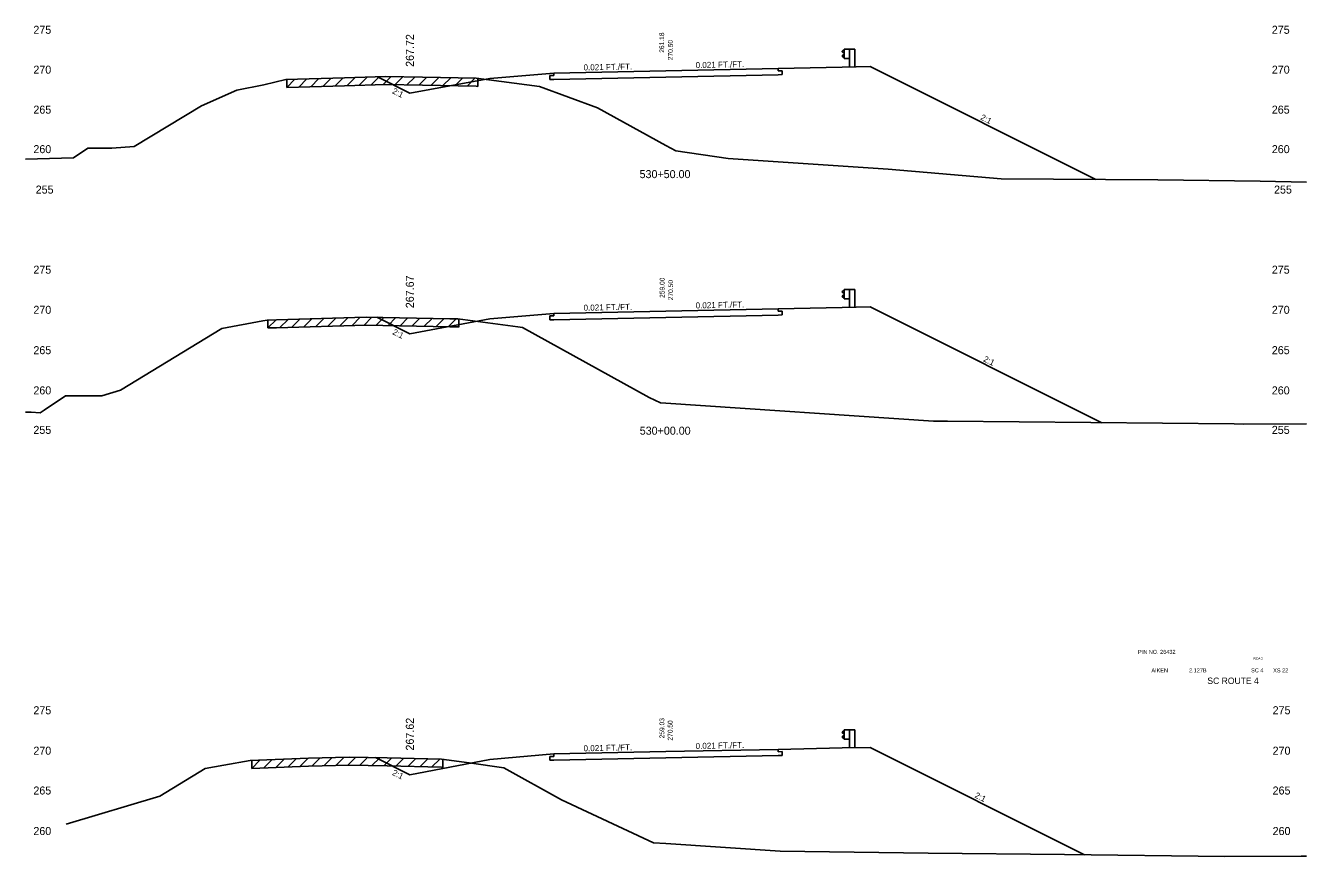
# Model space of a CAD drawing. Extents: x 883 to 1160, y 1002 to 4323.
# Drawn here: x 1000 to 1160, y 3492.4 to 3596.1 of the extents above; entities that cross this region are included whole.
import ezdxf

# ---------------------------------------------------------------- set-up
doc = ezdxf.new("R2010")
doc.units = 0
for name, color, linetype in [('Level 1', 7, 'Continuous'), ('Level 10', 7, 'Continuous'), ('Level 11', 7, 'Continuous'), ('Level 12', 7, 'Continuous'), ('Level 24', 7, 'Continuous'), ('Level 3', 7, 'Continuous'), ('Level 32', 7, 'Continuous'), ('Level 33', 7, 'Continuous'), ('Level 59', 7, 'Continuous'), ('Level 6', 7, 'Continuous'), ('Level 60', 7, 'Continuous'), ('Level 61', 7, 'Continuous'), ('Level 7', 7, 'Continuous')]:
    doc.layers.add(name, color=color, linetype=linetype)

msp = doc.modelspace()

# ---------------------------------------------------------------- linework, layer by layer
at = {"layer": 'Level 11'}
for p, q in [((1094, 3590.49), (1094, 3590.79)), ((1094.5, 3590.5), (1094, 3590.49)), ((1094.5, 3590.02), (1094.5, 3590.5)), ((1066, 3589.91), (1065.5, 3589.9)), ((1065.5, 3589.9), (1065.5, 3589.42)), ((1065.5, 3589.42), (1066, 3589.43)), ((1066, 3590.21), (1066, 3589.91)), ((1094, 3590.01), (1094.5, 3590.02)), ((1066, 3560.21), (1066, 3559.91)), ((1094, 3560.49), (1094, 3560.79)), ((1094.5, 3560.5), (1094, 3560.49)), ((1094, 3560.01), (1094.5, 3560.02)), ((1094.5, 3560.02), (1094.5, 3560.5)), ((1066, 3559.91), (1065.5, 3559.9)), ((1065.5, 3559.9), (1065.5, 3559.42)), ((1065.5, 3559.42), (1066, 3559.43)), ((1094, 3505.49), (1094, 3505.79)), ((1066, 3504.91), (1065.5, 3504.9)), ((1065.5, 3504.9), (1065.5, 3504.42)), ((1065.5, 3504.42), (1066, 3504.43)), ((1066, 3505.21), (1066, 3504.91)), ((1094.5, 3505.5), (1094, 3505.49)), ((1094, 3505.01), (1094.5, 3505.02)), ((1094.5, 3505.02), (1094.5, 3505.5))]:
    msp.add_line(p, q, dxfattribs=at)
at = {"layer": 'Level 12'}
for p, q in [((1080, 3589.72), (1066, 3589.43)), ((1094, 3590.01), (1080, 3589.72)), ((1094, 3560.01), (1080, 3559.72)), ((1080, 3559.72), (1066, 3559.43)), ((1080, 3504.72), (1066, 3504.43)), ((1094, 3505.01), (1080, 3504.72))]:
    msp.add_line(p, q, dxfattribs=at)
at = {"layer": 'Level 24'}
for p, q in [((1102.27, 3593.13), (1102, 3592.93)), ((1102, 3592.93), (1102, 3592.88)), ((1102, 3592.88), (1102.27, 3592.68)), ((1102, 3592.36), (1102.27, 3592.56)), ((1102, 3592.31), (1102, 3592.36)), ((1102.27, 3592.11), (1102, 3592.31)), ((1102.27, 3592.04), (1102.27, 3593.21)), ((1102.27, 3593.21), (1102.94, 3593.21)), ((1102.27, 3592.04), (1102.94, 3592.04)), ((1102.94, 3593.21), (1102.94, 3590.98)), ((1102.94, 3593.21), (1103.6, 3593.21)), ((1103.6, 3593.21), (1103.6, 3590.99)), ((1102.27, 3562.04), (1102.27, 3563.21)), ((1102.27, 3563.21), (1102.94, 3563.21)), ((1102.94, 3563.21), (1102.94, 3560.98)), ((1102.94, 3563.21), (1103.6, 3563.21)), ((1103.6, 3563.21), (1103.6, 3560.99)), ((1102.27, 3563.13), (1102, 3562.93)), ((1102, 3562.93), (1102, 3562.88)), ((1102, 3562.88), (1102.27, 3562.68)), ((1102, 3562.36), (1102.27, 3562.56)), ((1102, 3562.31), (1102, 3562.36)), ((1102.27, 3562.11), (1102, 3562.31)), ((1102.27, 3562.04), (1102.94, 3562.04)), ((1102.27, 3508.13), (1102, 3507.93)), ((1102, 3507.93), (1102, 3507.88)), ((1102, 3507.88), (1102.27, 3507.68)), ((1102, 3507.36), (1102.27, 3507.56)), ((1102, 3507.31), (1102, 3507.36)), ((1102.27, 3507.11), (1102, 3507.31)), ((1102.27, 3507.04), (1102.27, 3508.21)), ((1102.27, 3508.21), (1102.94, 3508.21)), ((1102.94, 3508.21), (1102.94, 3505.98)), ((1102.94, 3508.21), (1103.6, 3508.21)), ((1103.6, 3508.21), (1103.6, 3505.99)), ((1102.27, 3507.04), (1102.94, 3507.04))]:
    msp.add_line(p, q, dxfattribs=at)
at = {"layer": 'Level 59'}
for p, q in [((1066, 3590.21), (1080, 3590.5)), ((1080, 3590.5), (1094, 3590.79)), ((1066, 3560.21), (1080, 3560.5)), ((1080, 3560.5), (1094, 3560.79)), ((1080, 3505.5), (1094, 3505.79)), ((1066, 3505.21), (1080, 3505.5))]:
    msp.add_line(p, q, dxfattribs=at)
at = {"layer": 'Level 6'}
for p, q in [((1094, 3590.79), (1102, 3590.96)), ((1102, 3590.96), (1105.5, 3591.03)), ((1058, 3589.54), (1066, 3590.21)), ((1058, 3559.54), (1066, 3560.21)), ((1094, 3560.79), (1102, 3560.96)), ((1102, 3560.96), (1105.5, 3561.03)), ((1094, 3505.79), (1102, 3505.96)), ((1102, 3505.96), (1105.5, 3506.03)), ((1058, 3504.54), (1066, 3505.21))]:
    msp.add_line(p, q, dxfattribs=at)
at = {"layer": 'Level 60'}
for p, q in [((1029.78, 3588.74), (1032.49, 3589.4)), ((1032.49, 3589.4), (1039.84, 3589.62)), ((1039.84, 3589.62), (1044.97, 3589.77)), ((1044.97, 3589.77), (1049.56, 3589.7)), ((1049.56, 3589.7), (1056.28, 3589.56)), ((1056.28, 3589.56), (1059.45, 3589.15)), ((1059.45, 3589.15), (1064.2, 3588.53)), ((1021.96, 3586.13), (1026.38, 3588.1)), ((1026.38, 3588.1), (1029.78, 3588.74)), ((1064.2, 3588.53), (1071.46, 3585.88)), ((1013.58, 3581.05), (1021.96, 3586.13)), ((1071.46, 3585.88), (1080, 3581.18)), ((1005.98, 3579.65), (1007.78, 3580.84)), ((1007.78, 3580.84), (1010.77, 3580.84)), ((1010.77, 3580.84), (1013.58, 3581.05)), ((1080, 3581.18), (1081.21, 3580.51)), ((1000, 3579.48), (1005.98, 3579.65)), ((1081.21, 3580.51), (1087.78, 3579.53)), ((1087.78, 3579.53), (1107.77, 3578.22)), ((1107.77, 3578.22), (1121.85, 3577.01)), ((1121.85, 3577.01), (1141.44, 3576.87)), ((1141.44, 3576.87), (1154.24, 3576.73)), ((1154.24, 3576.73), (1160, 3576.59)), ((1024.5, 3558.32), (1029.63, 3559.29)), ((1029.63, 3559.29), (1030.16, 3559.38)), ((1030.16, 3559.38), (1031.34, 3559.43)), ((1031.34, 3559.43), (1042.55, 3559.76)), ((1042.55, 3559.76), (1053, 3559.54)), ((1053, 3559.54), (1053.98, 3559.52)), ((1053.98, 3559.52), (1061.49, 3558.52)), ((1061.49, 3558.52), (1062.08, 3558.44)), ((1062.08, 3558.44), (1077.9, 3549.7)), ((1011.84, 3550.64), (1024.5, 3558.32)), ((1009.51, 3549.94), (1011.84, 3550.64)), ((1002.3, 3548.14), (1005, 3549.94)), ((1005, 3549.94), (1009.51, 3549.94)), ((1077.9, 3549.7), (1079.32, 3549.04)), ((1079.32, 3549.04), (1080, 3549)), ((1080, 3549), (1113.42, 3546.77)), ((1000, 3547.87), (1000.7, 3547.88)), ((1000.7, 3547.88), (1001.8, 3547.78)), ((1001.8, 3547.78), (1002.3, 3548.14)), ((1113.42, 3546.77), (1115.15, 3546.74)), ((1115.15, 3546.74), (1150.98, 3546.41)), ((1150.98, 3546.41), (1152.2, 3546.4)), ((1152.2, 3546.4), (1160, 3546.43)), ((1024.76, 3503.83), (1028.05, 3504.4)), ((1028.05, 3504.4), (1035.36, 3504.68)), ((1035.36, 3504.68), (1040.44, 3504.83)), ((1040.44, 3504.83), (1045.17, 3504.73)), ((1045.17, 3504.73), (1051.97, 3504.56)), ((1051.97, 3504.56), (1055.39, 3504.1)), ((1055.39, 3504.1), (1059.73, 3503.48)), ((1016.77, 3499.94), (1022.45, 3503.4)), ((1022.45, 3503.4), (1024.76, 3503.83)), ((1059.73, 3503.48), (1066.96, 3499.48)), ((1005.07, 3496.43), (1016.77, 3499.94)), ((1066.96, 3499.48), (1078.44, 3494.13)), ((1078.44, 3494.13), (1080, 3494.03)), ((1080, 3494.03), (1094.26, 3493.08)), ((1094.26, 3493.08), (1112.77, 3492.83)), ((1112.77, 3492.83), (1129.77, 3492.67)), ((1129.77, 3492.67), (1149.8, 3492.43)), ((1149.8, 3492.43), (1159.33, 3492.47)), ((1159.33, 3492.47), (1160, 3492.47))]:
    msp.add_line(p, q, dxfattribs=at)
at = {"layer": 'Level 61'}
for p, q in [((1033.65, 3589.44), (1032.62, 3588.41)), ((1032.62, 3589.41), (1032.62, 3588.41)), ((1035.15, 3589.48), (1034.12, 3588.45)), ((1036.65, 3589.53), (1035.62, 3588.5)), ((1038.16, 3589.57), (1037.12, 3588.54)), ((1039.66, 3589.62), (1038.63, 3588.59)), ((1041.16, 3589.66), (1040.13, 3588.63)), ((1042.66, 3589.7), (1041.63, 3588.68)), ((1044.16, 3589.75), (1043.13, 3588.72)), ((1045.63, 3589.76), (1044.63, 3588.76)), ((1047.12, 3589.74), (1046.13, 3588.75)), ((1048.62, 3589.72), (1047.64, 3588.73)), ((1050.12, 3589.69), (1049.14, 3588.71)), ((1051.62, 3589.66), (1050.64, 3588.68)), ((1053.12, 3589.63), (1052.14, 3588.65)), ((1054.63, 3589.6), (1053.64, 3588.62)), ((1056.13, 3589.57), (1055.15, 3588.59)), ((1056.5, 3588.54), (1056.5, 3589.54)), ((1032.62, 3588.41), (1039.84, 3588.62)), ((1039.84, 3588.62), (1044.97, 3588.77)), ((1044.97, 3588.77), (1049.56, 3588.7)), ((1049.56, 3588.7), (1056.28, 3588.56)), ((1056.28, 3588.56), (1056.5, 3588.54)), ((1031.31, 3559.43), (1030.27, 3558.39)), ((1030.27, 3559.39), (1030.27, 3558.39)), ((1030.27, 3558.39), (1031.34, 3558.43)), ((1031.34, 3558.43), (1042.55, 3558.76)), ((1032.8, 3559.47), (1031.77, 3558.44)), ((1034.3, 3559.52), (1033.27, 3558.49)), ((1035.8, 3559.56), (1034.77, 3558.53)), ((1037.3, 3559.61), (1036.27, 3558.57)), ((1038.81, 3559.65), (1037.77, 3558.62)), ((1040.31, 3559.7), (1039.27, 3558.66)), ((1041.81, 3559.74), (1040.78, 3558.71)), ((1043.27, 3559.75), (1042.28, 3558.75)), ((1042.55, 3558.76), (1053, 3558.54)), ((1044.76, 3559.72), (1043.78, 3558.74)), ((1046.26, 3559.68), (1045.28, 3558.7)), ((1047.76, 3559.65), (1046.78, 3558.67)), ((1049.26, 3559.62), (1048.28, 3558.64)), ((1050.77, 3559.59), (1049.79, 3558.61)), ((1052.27, 3559.56), (1051.29, 3558.58)), ((1053.77, 3559.52), (1052.79, 3558.55)), ((1053, 3558.54), (1053.98, 3558.52)), ((1053.98, 3558.52), (1054.14, 3558.5)), ((1054.14, 3558.5), (1054.14, 3559.5)), ((1029.28, 3504.45), (1028.24, 3503.41)), ((1028.24, 3504.41), (1028.24, 3503.41)), ((1030.78, 3504.51), (1029.74, 3503.47)), ((1032.28, 3504.56), (1031.24, 3503.52)), ((1033.78, 3504.62), (1032.74, 3503.58)), ((1035.28, 3504.67), (1034.25, 3503.63)), ((1036.78, 3504.72), (1035.75, 3503.69)), ((1038.28, 3504.76), (1037.25, 3503.73)), ((1039.78, 3504.81), (1038.75, 3503.78)), ((1041.24, 3504.81), (1040.25, 3503.82)), ((1042.73, 3504.78), (1041.75, 3503.8)), ((1044.23, 3504.75), (1043.25, 3503.77)), ((1045.73, 3504.71), (1044.75, 3503.74)), ((1047.23, 3504.68), (1046.25, 3503.7)), ((1048.73, 3504.64), (1047.75, 3503.66)), ((1050.23, 3504.6), (1049.26, 3503.62)), ((1051.73, 3504.56), (1050.76, 3503.59)), ((1052.11, 3503.54), (1052.11, 3504.54)), ((1028.24, 3503.41), (1035.36, 3503.68)), ((1035.36, 3503.68), (1040.44, 3503.83)), ((1040.44, 3503.83), (1045.17, 3503.73)), ((1045.17, 3503.73), (1051.97, 3503.56)), ((1051.97, 3503.56), (1052.11, 3503.54))]:
    msp.add_line(p, q, dxfattribs=at)
at = {"layer": 'Level 7'}
for p, q in [((1105.5, 3591.03), (1133.71, 3576.92)), ((1043.95, 3589.74), (1048, 3587.72)), ((1048, 3587.72), (1058, 3589.54)), ((1105.5, 3561.03), (1134.43, 3546.56)), ((1043.86, 3559.73), (1048, 3557.67)), ((1048, 3557.67), (1058, 3559.54)), ((1105.5, 3506.03), (1132.28, 3492.64)), ((1043.72, 3504.76), (1048, 3502.62)), ((1048, 3502.62), (1058, 3504.54))]:
    msp.add_line(p, q, dxfattribs=at)

# ---------------------------------------------------------------- texts
at = {"layer": 'Level 1'}
for s, height, p in [('530+50.00', 1, (1076.7, 3577.1)), ('530+00.00', 1, (1076.72, 3545.07)), ('PIN NO. 26432', 0.5, (1138.97, 3517.71)), ('AIKEN', 0.5, (1140.64, 3515.4)), (' 2.127B', 0.5, (1145.15, 3515.4)), ('SC 4', 0.5, (1153.09, 3515.4)), ('XS 22', 0.5, (1155.85, 3515.39)), ('SC ROUTE 4', 0.8, (1147.63, 3513.95))]:
    msp.add_text(s, height=height, dxfattribs=at).set_placement(p)
at = {"layer": 'Level 10'}
for s, p in [('261.18', (1079.77, 3592.75)), ('259.00', (1079.82, 3562.15)), ('259.03', (1079.79, 3507.16))]:
    msp.add_text(s, height=0.6, rotation=90, dxfattribs=at).set_placement(p)
at = {"layer": 'Level 3'}
for s, height, p in [(' 275', 1, (1000.6, 3595.12)), (' 275', 1, (1155.31, 3595.12)), (' 270', 1, (1000.6, 3590.14)), (' 270', 1, (1155.31, 3590.14)), (' 265', 1, (1000.6, 3585.15)), (' 265', 1, (1155.31, 3585.15)), (' 260', 1, (1000.6, 3580.22)), (' 260', 1, (1155.31, 3580.22)), (' 255', 1, (1000.89, 3575.17)), (' 255', 1, (1155.59, 3575.17)), (' 275', 1, (1000.6, 3565.17)), (' 275', 1, (1155.31, 3565.17)), (' 270', 1, (1000.6, 3560.16)), (' 270', 1, (1155.31, 3560.16)), (' 265', 1, (1000.6, 3555.12)), (' 265', 1, (1155.31, 3555.12)), (' 260', 1, (1000.6, 3550.1)), (' 260', 1, (1155.31, 3550.1)), (' 255', 1, (1000.6, 3545.17)), (' 255', 1, (1155.31, 3545.17)), ('ROAD', 0.3, (1153.38, 3516.98)), (' 275', 1, (1000.6, 3510.17)), (' 275', 1, (1155.41, 3510.17)), (' 270', 1, (1000.6, 3505.12)), (' 270', 1, (1155.41, 3505.12)), (' 265', 1, (1000.6, 3500.15)), (' 265', 1, (1155.41, 3500.15)), (' 260', 1, (1000.6, 3495.09)), (' 260', 1, (1155.41, 3495.09))]:
    msp.add_text(s, height=height, dxfattribs=at).set_placement(p)
at = {"layer": 'Level 32'}
for s, rotation, p in [('0.021 FT./FT.', 1.1916, (1069.71, 3590.54)), ('0.021 FT./FT.', 1.1916, (1083.71, 3590.83)), ('2:1', 333.435, (1045.73, 3587.73)), ('2:1', 333.435, (1119.21, 3584.45)), ('0.021 FT./FT.', 1.1916, (1083.71, 3560.83)), ('0.021 FT./FT.', 1.1916, (1069.71, 3560.54)), ('2:1', 333.435, (1045.76, 3557.65)), ('2:1', 333.435, (1119.57, 3554.27)), ('0.021 FT./FT.', 1.1916, (1069.71, 3505.54)), ('0.021 FT./FT.', 1.1916, (1083.71, 3505.83)), ('2:1', 333.435, (1045.73, 3502.63)), ('2:1', 333.435, (1118.49, 3499.81))]:
    msp.add_text(s, height=0.75, rotation=rotation, dxfattribs=at).set_placement(p)
at = {"layer": 'Level 33'}
for s, p in [('267.72', (1048.5, 3590.99)), ('267.67', (1048.5, 3560.86)), ('267.62', (1048.5, 3505.64))]:
    msp.add_text(s, height=1, rotation=90, dxfattribs=at).set_placement(p)
at = {"layer": 'Level 59'}
for p in [(1080.85, 3591.59), (1080.88, 3561.62), (1080.82, 3506.65)]:
    msp.add_text(' 270.50', height=0.6, rotation=90, dxfattribs=at).set_placement(p)

doc.saveas('drawing.dxf')
